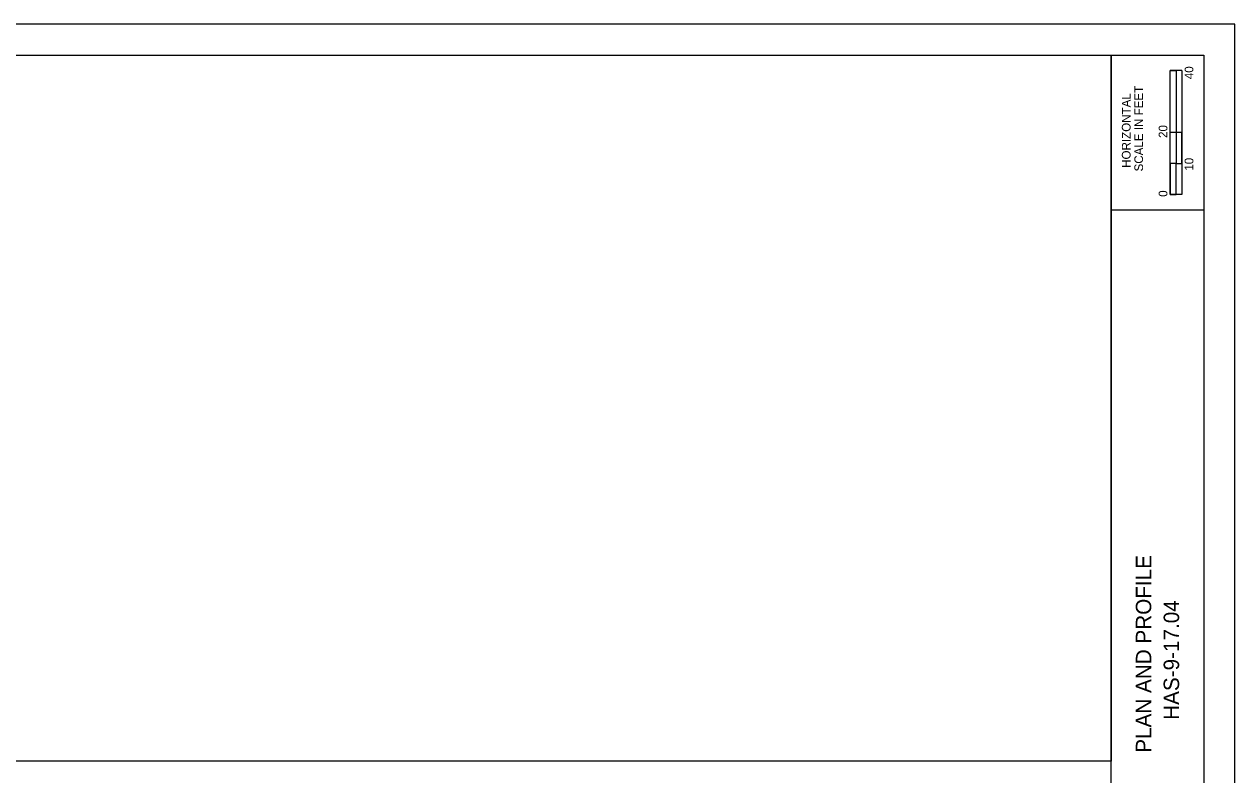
# Model space of a CAD drawing. Extents: x -5960 to 34, y -2569 to 22.
# Drawn here: x 14.43 to 34, y 9.87 to 22 of the extents above; entities that cross this region are included whole.
import ezdxf

# ---------------------------------------------------------------- set-up
doc = ezdxf.new("R2010")
doc.units = 0
for name, color, linetype in [('GT_Instrumented_Soil_Boring', 7, 'Continuous'), ('SN_X_Public', 7, 'Continuous'), ('SV_X_Mon_Cells_Found', 7, 'Continuous'), ('SV_X_Shot_Marker', 7, 'Continuous')]:
    doc.layers.add(name, color=color, linetype=linetype)

msp = doc.modelspace()

# ---------------------------------------------------------------- linework, layer by layer
at = {"layer": 'GT_Instrumented_Soil_Boring'}
for p, q in [((32.957, 19.25), (32.957, 21.25)), ((33.144, 21.25), (32.957, 21.25)), ((32.957, 20.25), (32.957, 21.25)), ((32.957, 21.25), (33.05, 21.25)), ((33.05, 21.25), (33.051, 21.25)), ((33.051, 21.25), (33.051, 20.25)), ((33.144, 21.25), (33.144, 19.25)), ((33.051, 20.25), (32.957, 20.25)), ((33.143, 20.25), (33.05, 20.25)), ((33.05, 20.25), (33.05, 19.75)), ((33.143, 19.75), (33.143, 20.25)), ((33.05, 19.75), (32.957, 19.75)), ((32.957, 19.75), (32.957, 19.25)), ((33.05, 19.25), (33.05, 19.75)), ((33.05, 19.75), (33.143, 19.75)), ((33.144, 19.25), (32.957, 19.25)), ((32.957, 19.25), (33.05, 19.25))]:
    msp.add_line(p, q, dxfattribs=at)
at = {"layer": 'SN_X_Public'}
msp.add_lwpolyline([(1.5, 21.5), (32, 21.5), (32, 10.091), (1.5, 10.091)], close=True, dxfattribs=at)
at = {"layer": 'SV_X_Mon_Cells_Found'}
msp.add_lwpolyline([(0, 0), (34, 0), (34, 22), (0, 22)], close=True, dxfattribs=at)
at = {"layer": 'SV_X_Shot_Marker'}
for p, q in [((32, 0.5), (32, 21.5)), ((32, 19), (33.5, 19))]:
    msp.add_line(p, q, dxfattribs=at)
msp.add_lwpolyline([(1.5, 21.5), (33.5, 21.5), (33.5, 0.5), (1.5, 0.5)], close=True, dxfattribs=at)

# ---------------------------------------------------------------- texts
at = {"layer": 'GT_Instrumented_Soil_Boring'}
for s, height, p in [('40', 0.14, (33.33, 21.112)), ('SCALE IN FEET', 0.14, (32.517, 19.621)), ('HORIZONTAL', 0.14, (32.315, 19.679)), ('20', 0.14, (32.91, 20.162)), ('10', 0.14, (33.33, 19.633)), ('0', 0.14, (32.91, 19.211)), ('PLAN AND PROFILE', 0.25, (32.65, 10.227)), ('HAS-9-17.04', 0.25, (33.1, 10.759))]:
    msp.add_text(s, height=height, rotation=90, dxfattribs=at).set_placement(p)

doc.saveas('drawing.dxf')
